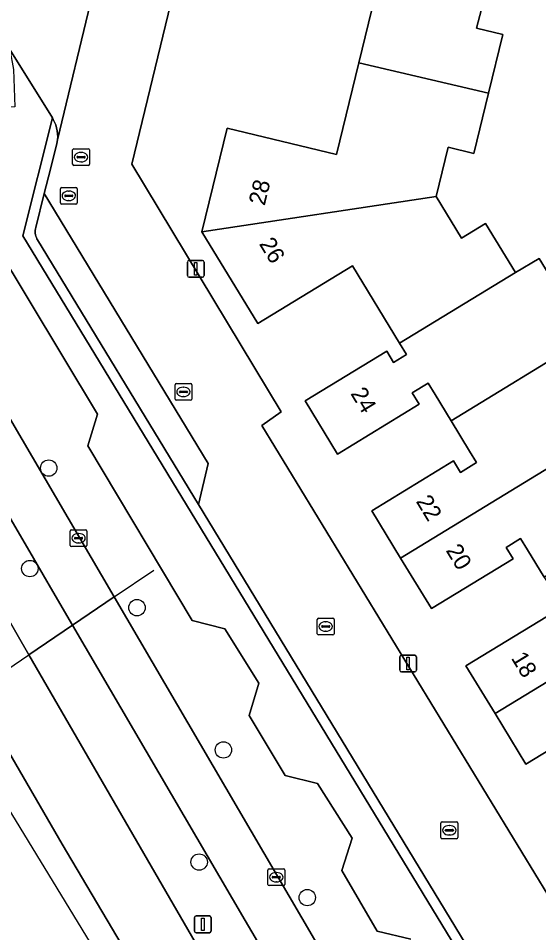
# Model space of a CAD drawing. Extents: x 157767 to 159172, y 387839 to 389425.
# Drawn here: x 158129.2 to 158160.3, y 388348.6 to 388403.1 of the extents above; entities that cross this region are included whole.
import ezdxf

# ---------------------------------------------------------------- set-up
doc = ezdxf.new("R2010")
doc.units = 0
for name, color, linetype in [('IMGEO_Berm_groen', 7, 'Continuous'), ('IMGEO_Boom', 7, 'Continuous'), ('IMGEO_Duiker', 7, 'Continuous'), ('IMGEO_Erf', 7, 'Continuous'), ('IMGEO_Fietspad_gesloten', 7, 'Continuous'), ('IMGEO_Fietspad_open', 7, 'Continuous'), ('IMGEO_Groenvoorziening', 7, 'Continuous'), ('IMGEO_Kolk', 7, 'Continuous'), ('IMGEO_Lichtmast', 7, 'Continuous'), ('IMGEO_Muur', 7, 'Continuous'), ('IMGEO_Pand', 7, 'Continuous'), ('IMGEO_Pand_nummerreeks', 7, 'Continuous'), ('IMGEO_Parkeervlak_open', 7, 'Continuous'), ('IMGEO_Rijbaan_lokaal_open', 7, 'Continuous'), ('IMGEO_Rijbaan_regionaal_gesloten', 7, 'Continuous'), ('IMGEO_Rioolput', 7, 'Continuous'), ('IMGEO_Voetpad_open', 7, 'Continuous')]:
    doc.layers.add(name, color=color, linetype=linetype)

msp = doc.modelspace()

# ---------------------------------------------------------------- linework, layer by layer
at = {"layer": 'IMGEO_Berm_groen'}
for points in [[(158093.596, 388437.697), (158077.696, 388467.86), (158066.3, 388489.348), (158060.675, 388500), (158059.824, 388501.559), (158060.092, 388498.304), (158060.284, 388498.409), (158061.294, 388496.567), (158060.28, 388496.011), (158060.757, 388490.208), (158067.746, 388475.595), (158073.282, 388464.018), (158077.309, 388457.044), (158080.74, 388450.845), (158117.028, 388387.52), (158126.188, 388371.462), (158129.845, 388365.121), (158132.45, 388366.885), (158131.292, 388368.887), (158130.136, 388370.89), (158116.54, 388394.144), (158109.829, 388406.303), (158099.787, 388425.751)], [(158153.286, 388331.356), (158142.759, 388349.282), (158132.45, 388366.885), (158129.845, 388365.121), (158139.769, 388348), (158157.789, 388317.741), (158173.795, 388291.448), (158178.959, 388283.153), (158180.756, 388284.205), (158178.868, 388289.086), (158165.181, 388311.658)]]:
    msp.add_lwpolyline(points, close=True, dxfattribs=at)
at = {"layer": 'IMGEO_Boom'}
for centre in [(158131.037, 388376.248), (158129.913, 388370.263), (158136.3, 388367.931), (158141.455, 388359.45), (158140.006, 388352.769), (158146.455, 388350.649)]:
    msp.add_circle(centre, 0.489, dxfattribs=at)
at = {"layer": 'IMGEO_Duiker'}
msp.add_lwpolyline([(158125.103, 388361.908), (158125.146, 388361.937), (158126.715, 388363), (158129.845, 388365.121), (158132.45, 388366.885), (158134.936, 388368.569), (158137.301, 388370.172)], dxfattribs=at)
at = {"layer": 'IMGEO_Erf'}
for points in [[(158141.098, 388415.471), (158135.994, 388394.364), (158144.897, 388379.594), (158143.742, 388378.793), (158169.317, 388336.817)], [(158160.58, 388369.753), (158159.594, 388371.37), (158159.177, 388372.054), (158158.306, 388371.523), (158158.722, 388370.839), (158153.854, 388367.872), (158152.017, 388370.886), (158150.297, 388373.709), (158155.165, 388376.676), (158155.582, 388375.993), (158156.545, 388376.58), (158156.129, 388377.263), (158155.027, 388379.072), (158154.073, 388380.638), (158153.657, 388381.322), (158152.702, 388380.74), (158153.118, 388380.056), (158148.25, 388377.09), (158146.319, 388380.259), (158151.188, 388383.226), (158151.604, 388382.543), (158152.376, 388383.014), (158151.961, 388383.695), (158149.147, 388388.314), (158143.498, 388384.871), (158140.169, 388390.335), (158141.671, 388396.521), (158148.204, 388394.933), (158149.535, 388400.41), (158150.867, 388405.887)], [(158157.317, 388405.425), (158156.544, 388402.467), (158158.109, 388402.086), (158157.261, 388398.598), (158156.388, 388395.006), (158154.849, 388395.38), (158154.131, 388392.43), (158155.645, 388389.947), (158157.089, 388390.827), (158158.87, 388387.903), (158160.28, 388388.751), (158163.159, 388384.027), (158165.981, 388379.396), (158168.803, 388374.765), (158171.625, 388370.134), (158174.978, 388372.178), (158177.801, 388367.546), (158174.448, 388365.502), (158177.27, 388360.871), (158180.092, 388356.24), (158182.914, 388351.609), (158185.8, 388346.873)], [(158164.35, 388361.572), (158159.482, 388358.605), (158157.648, 388361.615), (158155.916, 388364.457), (158160.784, 388367.424)]]:
    msp.add_lwpolyline(points, dxfattribs=at)
at = {"layer": 'IMGEO_Fietspad_gesloten'}
msp.add_lwpolyline([(158077.696, 388467.86), (158093.596, 388437.697), (158099.787, 388425.751), (158109.829, 388406.303), (158116.54, 388394.144), (158130.136, 388370.89), (158131.292, 388368.887), (158132.45, 388366.885), (158134.936, 388368.569), (158119.086, 388395.663), (158117.484, 388398.656), (158113.772, 388405.372), (158099.445, 388433.055), (158096.584, 388438.321), (158064.182, 388500)], dxfattribs=at)
msp.add_lwpolyline([(158175.742, 388299.912), (158162.359, 388321.986), (158152.031, 388339.346), (158134.936, 388368.569), (158132.45, 388366.885), (158142.759, 388349.282), (158153.286, 388331.356), (158165.181, 388311.658), (158178.868, 388289.086), (158188.453, 388273.59), (158199.34, 388257.164), (158201.801, 388253.451), (158204.172, 388250), (158207.773, 388244.758), (158210.203, 388246.361), (158201.818, 388258.573), (158195.13, 388268.765), (158188.418, 388279.263)], close=True, dxfattribs=at)
at = {"layer": 'IMGEO_Fietspad_open'}
msp.add_lwpolyline([(158109.579, 388433.031), (158117.583, 388419.75), (158128.726, 388401.202), (158131.254, 388397.124), (158131.309, 388397.033), (158131.391, 388396.872), (158131.459, 388396.705), (158131.511, 388396.533), (158131.548, 388396.356), (158131.569, 388396.177), (158131.573, 388395.997), (158131.562, 388395.817), (158133.657, 388404.502)], dxfattribs=at)
at = {"layer": 'IMGEO_Groenvoorziening'}
for points in [[(158108.113, 388434.305), (158101.745, 388435.024), (158101.62, 388435.033), (158101.495, 388435.03), (158101.37, 388435.016), (158101.248, 388434.991), (158101.127, 388434.956), (158101.011, 388434.909), (158100.899, 388434.853), (158100.793, 388434.787), (158100.693, 388434.711), (158100.6, 388434.627), (158100.515, 388434.535), (158100.449, 388434.45), (158099.445, 388433.055), (158113.772, 388405.372), (158117.484, 388398.656), (158119.086, 388395.663), (158134.936, 388368.569), (158152.031, 388339.346)], [(158175.446, 388314.592), (158129.494, 388390.09), (158131.254, 388397.124), (158128.726, 388401.202), (158128.931, 388400.006), (158129.021, 388397.788), (158127.944, 388397.706), (158126.885, 388397.853), (158125.71, 388393.121), (158133.951, 388379.467), (158133.376, 388377.573), (158139.588, 388367.158), (158141.543, 388366.666), (158143.57, 388363.424), (158142.99, 388361.495), (158145.126, 388357.922), (158147.067, 388357.45), (158149.128, 388354.196), (158148.513, 388352.268), (158150.628, 388348.658), (158152.625, 388348.163)], [(158152.625, 388348.163), (158150.628, 388348.658), (158148.513, 388352.268), (158149.128, 388354.196), (158147.067, 388357.45), (158145.126, 388357.922), (158142.99, 388361.495), (158143.57, 388363.424), (158141.543, 388366.666), (158139.588, 388367.158), (158133.376, 388377.573), (158133.951, 388379.467), (158125.71, 388393.121), (158126.885, 388397.853)]]:
    msp.add_lwpolyline(points, dxfattribs=at)
at = {"layer": 'IMGEO_Kolk'}
for p, q in [((158132.539, 388395.285), (158133.391, 388395.285)), ((158132.464, 388394.359), (158132.464, 388395.211)), ((158132.723, 388394.779), (158132.723, 388394.791)), ((158133.161, 388394.742), (158132.763, 388394.742)), ((158132.766, 388394.828), (158133.164, 388394.828)), ((158132.952, 388395.065), (158132.977, 388395.065)), ((158133.207, 388394.791), (158133.207, 388394.779)), ((158133.465, 388395.211), (158133.465, 388394.359)), ((158133.391, 388394.285), (158132.539, 388394.285)), ((158132.975, 388394.505), (158132.95, 388394.505)), ((158138.567, 388380.365), (158138.567, 388381.217)), ((158138.642, 388381.291), (158139.494, 388381.291)), ((158139.568, 388381.217), (158139.568, 388380.365)), ((158138.826, 388380.785), (158138.826, 388380.797)), ((158139.264, 388380.748), (158138.866, 388380.748)), ((158138.869, 388380.834), (158139.267, 388380.834)), ((158139.055, 388381.071), (158139.08, 388381.071)), ((158139.31, 388380.797), (158139.31, 388380.785)), ((158139.494, 388380.291), (158138.642, 388380.291)), ((158139.078, 388380.511), (158139.053, 388380.511)), ((158132.318, 388371.645), (158132.318, 388372.497)), ((158132.393, 388372.571), (158133.245, 388372.571)), ((158133.319, 388372.497), (158133.319, 388371.645)), ((158132.577, 388372.065), (158132.577, 388372.077)), ((158133.015, 388372.028), (158132.617, 388372.028)), ((158132.62, 388372.114), (158133.018, 388372.114)), ((158132.806, 388372.351), (158132.831, 388372.351)), ((158133.061, 388372.077), (158133.061, 388372.065)), ((158133.245, 388371.571), (158132.393, 388371.571)), ((158132.829, 388371.791), (158132.804, 388371.791)), ((158147.053, 388366.381), (158147.053, 388367.233)), ((158147.128, 388367.307), (158147.98, 388367.307)), ((158147.541, 388367.087), (158147.566, 388367.087)), ((158148.054, 388367.233), (158148.054, 388366.381)), ((158147.312, 388366.801), (158147.312, 388366.813)), ((158147.75, 388366.764), (158147.352, 388366.764)), ((158147.355, 388366.85), (158147.753, 388366.85)), ((158147.564, 388366.527), (158147.539, 388366.527)), ((158147.796, 388366.813), (158147.796, 388366.801)), ((158147.98, 388366.307), (158147.128, 388366.307)), ((158154.423, 388354.235), (158154.423, 388355.087)), ((158154.498, 388355.161), (158155.35, 388355.161)), ((158154.911, 388354.941), (158154.936, 388354.941)), ((158155.424, 388355.087), (158155.424, 388354.235)), ((158154.682, 388354.655), (158154.682, 388354.667)), ((158155.12, 388354.618), (158154.722, 388354.618)), ((158154.725, 388354.704), (158155.123, 388354.704)), ((158154.934, 388354.381), (158154.909, 388354.381)), ((158155.166, 388354.667), (158155.166, 388354.655)), ((158155.35, 388354.161), (158154.498, 388354.161)), ((158144.108, 388351.439), (158144.108, 388352.291)), ((158144.183, 388352.365), (158145.035, 388352.365)), ((158145.109, 388352.291), (158145.109, 388351.439)), ((158144.367, 388351.859), (158144.367, 388351.871)), ((158144.805, 388351.822), (158144.407, 388351.822)), ((158144.41, 388351.908), (158144.808, 388351.908)), ((158144.596, 388352.145), (158144.621, 388352.145)), ((158144.851, 388351.871), (158144.851, 388351.859)), ((158145.035, 388351.365), (158144.183, 388351.365)), ((158144.619, 388351.585), (158144.594, 388351.585))]:
    msp.add_line(p, q, dxfattribs=at)
for points in [[(158132.539, 388395.285), (158133.391, 388395.285)], [(158132.464, 388394.359), (158132.464, 388395.211)], [(158133.465, 388395.211), (158133.465, 388394.359)], [(158133.391, 388394.285), (158132.539, 388394.285)], [(158138.567, 388380.365), (158138.567, 388381.217)], [(158138.642, 388381.291), (158139.494, 388381.291)], [(158139.568, 388381.217), (158139.568, 388380.365)], [(158139.494, 388380.291), (158138.642, 388380.291)], [(158132.318, 388371.645), (158132.318, 388372.497)], [(158132.393, 388372.571), (158133.245, 388372.571)], [(158133.319, 388372.497), (158133.319, 388371.645)], [(158133.245, 388371.571), (158132.393, 388371.571)], [(158147.053, 388366.381), (158147.053, 388367.233)], [(158147.128, 388367.307), (158147.98, 388367.307)], [(158148.054, 388367.233), (158148.054, 388366.381)], [(158147.98, 388366.307), (158147.128, 388366.307)], [(158154.423, 388354.235), (158154.423, 388355.087)], [(158154.498, 388355.161), (158155.35, 388355.161)], [(158155.424, 388355.087), (158155.424, 388354.235)], [(158155.35, 388354.161), (158154.498, 388354.161)], [(158144.108, 388351.439), (158144.108, 388352.291)], [(158144.183, 388352.365), (158145.035, 388352.365)], [(158145.109, 388352.291), (158145.109, 388351.439)], [(158145.035, 388351.365), (158144.183, 388351.365)]]:
    msp.add_lwpolyline(points, dxfattribs=at)
for centre, radius, start, end in [((158132.541, 388395.209), 0.0765, 91.552, 178.448), ((158132.541, 388395.209), 0.0765, 91.552, 178.448), ((158133.389, 388395.209), 0.0765, 1.552, 88.448), ((158133.389, 388395.209), 0.0765, 1.552, 88.448), ((158132.763, 388394.788), 0.0403, 85.8775, 175.7526), ((158132.76, 388394.778), 0.0366, 178.938, 274.7102), ((158133.164, 388394.785), 0.043, 264.8664, 352.4533), ((158133.168, 388394.79), 0.0386, 1.7309, 96.639), ((158132.541, 388394.361), 0.0765, 181.552, 268.448), ((158132.541, 388394.361), 0.0765, 181.552, 268.448), ((158133.389, 388394.361), 0.0765, 271.552, 358.448), ((158133.389, 388394.361), 0.0765, 271.552, 358.448), ((158138.644, 388381.215), 0.0765, 91.552, 178.448), ((158138.644, 388381.215), 0.0765, 91.552, 178.448), ((158139.492, 388381.215), 0.0765, 1.552, 88.448), ((158139.492, 388381.215), 0.0765, 1.552, 88.448), ((158138.866, 388380.794), 0.0403, 85.8775, 175.7526), ((158138.863, 388380.784), 0.0366, 178.938, 274.7102), ((158139.267, 388380.791), 0.043, 264.8664, 352.4533), ((158139.271, 388380.796), 0.0386, 1.7309, 96.639), ((158138.644, 388380.367), 0.0765, 181.552, 268.448), ((158138.644, 388380.367), 0.0765, 181.552, 268.448), ((158139.492, 388380.367), 0.0765, 271.552, 358.448), ((158139.492, 388380.367), 0.0765, 271.552, 358.448), ((158132.395, 388372.495), 0.0765, 91.552, 178.448), ((158132.395, 388372.495), 0.0765, 91.552, 178.448), ((158133.243, 388372.495), 0.0765, 1.552, 88.448), ((158133.243, 388372.495), 0.0765, 1.552, 88.448), ((158132.617, 388372.074), 0.0403, 85.8775, 175.7526), ((158132.614, 388372.064), 0.0366, 178.938, 274.7102), ((158133.018, 388372.071), 0.043, 264.8664, 352.4533), ((158133.022, 388372.076), 0.0386, 1.7309, 96.639), ((158132.395, 388371.647), 0.0765, 181.552, 268.448), ((158132.395, 388371.647), 0.0765, 181.552, 268.448), ((158133.243, 388371.647), 0.0765, 271.552, 358.448), ((158133.243, 388371.647), 0.0765, 271.552, 358.448), ((158147.13, 388367.231), 0.0765, 91.552, 178.448), ((158147.13, 388367.231), 0.0765, 91.552, 178.448), ((158147.978, 388367.231), 0.0765, 1.552, 88.448), ((158147.978, 388367.231), 0.0765, 1.552, 88.448), ((158147.13, 388366.383), 0.0765, 181.552, 268.448), ((158147.13, 388366.383), 0.0765, 181.552, 268.448), ((158147.352, 388366.81), 0.0403, 85.8775, 175.7526), ((158147.349, 388366.8), 0.0366, 178.938, 274.7102), ((158147.753, 388366.807), 0.043, 264.8664, 352.4533), ((158147.757, 388366.812), 0.0386, 1.7309, 96.639), ((158147.978, 388366.383), 0.0765, 271.552, 358.448), ((158147.978, 388366.383), 0.0765, 271.552, 358.448), ((158154.5, 388355.085), 0.0765, 91.552, 178.448), ((158154.5, 388355.085), 0.0765, 91.552, 178.448), ((158155.348, 388355.085), 0.0765, 1.552, 88.448), ((158155.348, 388355.085), 0.0765, 1.552, 88.448), ((158154.722, 388354.664), 0.0403, 85.8775, 175.7526), ((158154.719, 388354.654), 0.0366, 178.938, 274.7102), ((158155.123, 388354.661), 0.043, 264.8664, 352.4533), ((158155.127, 388354.666), 0.0386, 1.7309, 96.639), ((158154.5, 388354.237), 0.0765, 181.552, 268.448), ((158154.5, 388354.237), 0.0765, 181.552, 268.448), ((158155.348, 388354.237), 0.0765, 271.552, 358.448), ((158155.348, 388354.237), 0.0765, 271.552, 358.448), ((158144.185, 388352.289), 0.0765, 91.552, 178.448), ((158144.185, 388352.289), 0.0765, 91.552, 178.448), ((158145.033, 388352.289), 0.0765, 1.552, 88.448), ((158145.033, 388352.289), 0.0765, 1.552, 88.448), ((158144.407, 388351.868), 0.0403, 85.8775, 175.7526), ((158144.404, 388351.858), 0.0366, 178.938, 274.7102), ((158144.808, 388351.865), 0.043, 264.8664, 352.4533), ((158144.812, 388351.87), 0.0386, 1.7309, 96.639), ((158144.185, 388351.441), 0.0765, 181.552, 268.448), ((158144.185, 388351.441), 0.0765, 181.552, 268.448), ((158145.033, 388351.441), 0.0765, 271.552, 358.448), ((158145.033, 388351.441), 0.0765, 271.552, 358.448)]:
    msp.add_arc(centre, radius, start, end, dxfattribs=at)
for centre, major_axis, ratio, start_param, end_param in [((158132.951, 388394.785), (-0.387, 0.002), 0.722429, 4.712389, 7.853982), ((158132.976, 388394.785), (-0.39, 0.002), 0.717154, 1.570796, 4.712389), ((158139.054, 388380.791), (-0.387, 0.002), 0.722429, 4.712389, 7.853982), ((158139.079, 388380.791), (-0.39, 0.002), 0.717154, 1.570796, 4.712389), ((158132.805, 388372.071), (-0.387, 0.002), 0.722429, 4.712389, 7.853982), ((158132.83, 388372.071), (-0.39, 0.002), 0.717154, 1.570796, 4.712389), ((158147.54, 388366.807), (-0.387, 0.002), 0.722429, 4.712389, 7.853982), ((158147.565, 388366.807), (-0.39, 0.002), 0.717154, 1.570796, 4.712389), ((158154.91, 388354.661), (-0.387, 0.002), 0.722429, 4.712389, 7.853982), ((158154.935, 388354.661), (-0.39, 0.002), 0.717154, 1.570796, 4.712389), ((158144.595, 388351.865), (-0.387, 0.002), 0.722429, 4.712389, 7.853982), ((158144.62, 388351.865), (-0.39, 0.002), 0.717154, 1.570796, 4.712389)]:
    msp.add_ellipse(centre, major_axis=major_axis, ratio=ratio, start_param=start_param, end_param=end_param, dxfattribs=at)
at = {"layer": 'IMGEO_Lichtmast'}
for p, q in [((158139.308, 388387.73), (158139.308, 388388.53)), ((158139.308, 388388.53), (158139.308, 388387.73)), ((158139.408, 388388.63), (158140.198, 388388.63)), ((158140.198, 388388.63), (158139.408, 388388.63)), ((158140.298, 388388.53), (158140.298, 388387.73)), ((158140.298, 388387.73), (158140.298, 388388.53)), ((158140.198, 388387.63), (158139.408, 388387.63)), ((158139.408, 388387.63), (158140.198, 388387.63)), ((158151.968, 388364.199), (158151.968, 388364.999)), ((158151.968, 388364.999), (158151.968, 388364.199)), ((158152.068, 388365.099), (158152.858, 388365.099)), ((158152.858, 388365.099), (158152.068, 388365.099)), ((158152.958, 388364.999), (158152.958, 388364.199)), ((158152.958, 388364.199), (158152.958, 388364.999)), ((158152.858, 388364.099), (158152.068, 388364.099)), ((158152.068, 388364.099), (158152.858, 388364.099)), ((158139.828, 388349.556), (158140.618, 388349.556)), ((158140.618, 388349.556), (158139.828, 388349.556)), ((158139.728, 388348.656), (158139.728, 388349.456)), ((158139.728, 388349.456), (158139.728, 388348.656)), ((158140.718, 388349.456), (158140.718, 388348.656)), ((158140.718, 388348.656), (158140.718, 388349.456)), ((158140.618, 388348.556), (158139.828, 388348.556)), ((158139.828, 388348.556), (158140.618, 388348.556))]:
    msp.add_line(p, q, dxfattribs=at)
for points in [[(158139.728, 388388.505), (158139.878, 388388.505), (158139.878, 388387.755), (158139.728, 388387.755), (158139.728, 388388.505)], [(158152.388, 388364.974), (158152.538, 388364.974), (158152.538, 388364.224), (158152.388, 388364.224), (158152.388, 388364.974)], [(158140.148, 388349.431), (158140.298, 388349.431), (158140.298, 388348.681), (158140.148, 388348.681), (158140.148, 388349.431)]]:
    msp.add_lwpolyline(points, dxfattribs=at)
for centre, start, end in [((158139.408, 388388.53), 90, 180), ((158139.408, 388388.53), 90, 180), ((158140.198, 388388.53), 0, 90), ((158140.198, 388388.53), 360, 90), ((158139.408, 388387.73), 180, 270), ((158139.408, 388387.73), 180, 270), ((158140.198, 388387.73), 270, 0), ((158140.198, 388387.73), 270, 0), ((158152.068, 388364.999), 90, 180), ((158152.068, 388364.999), 90, 180), ((158152.858, 388364.999), 0, 90), ((158152.858, 388364.999), 360, 90), ((158152.068, 388364.199), 180, 270), ((158152.068, 388364.199), 180, 270), ((158152.858, 388364.199), 270, 0), ((158152.858, 388364.199), 270, 0), ((158139.828, 388349.456), 90, 180), ((158139.828, 388349.456), 90, 180), ((158140.618, 388349.456), 0, 90), ((158140.618, 388349.456), 360, 90), ((158139.828, 388348.656), 180, 270), ((158139.828, 388348.656), 180, 270), ((158140.618, 388348.656), 270, 0), ((158140.618, 388348.656), 270, 0)]:
    msp.add_arc(centre, 0.1, start, end, dxfattribs=at)
at = {"layer": 'IMGEO_Muur'}
msp.add_lwpolyline([(158126.885, 388397.853), (158125.71, 388393.121), (158133.951, 388379.467), (158133.376, 388377.573), (158139.588, 388367.158), (158141.543, 388366.666), (158143.57, 388363.424), (158142.99, 388361.495), (158145.126, 388357.922), (158147.067, 388357.45), (158149.128, 388354.196), (158148.513, 388352.268), (158150.628, 388348.658), (158152.625, 388348.163)], dxfattribs=at)
at = {"layer": 'IMGEO_Pand'}
for points in [[(158149.535, 388400.41), (158157.261, 388398.598), (158158.109, 388402.086), (158156.544, 388402.467), (158157.317, 388405.425), (158145.839, 388413.615), (158144.346, 388407.472), (158150.867, 388405.887)], [(158140.169, 388390.335), (158154.131, 388392.43), (158154.849, 388395.38), (158156.388, 388395.006), (158157.261, 388398.598), (158149.535, 388400.41), (158148.204, 388394.933), (158141.671, 388396.521)], [(158140.169, 388390.335), (158143.498, 388384.871), (158149.147, 388388.314), (158151.961, 388383.695), (158158.87, 388387.903), (158157.089, 388390.827), (158155.645, 388389.947), (158154.131, 388392.43)], [(158163.159, 388384.027), (158160.28, 388388.751), (158158.87, 388387.903), (158151.961, 388383.695), (158152.376, 388383.014), (158151.604, 388382.543), (158151.188, 388383.226), (158146.319, 388380.259), (158148.25, 388377.09), (158153.118, 388380.056), (158152.702, 388380.74), (158153.657, 388381.322), (158154.073, 388380.638), (158155.027, 388379.072)], [(158163.159, 388384.027), (158155.027, 388379.072), (158156.129, 388377.263), (158156.545, 388376.58), (158155.582, 388375.993), (158155.165, 388376.676), (158150.297, 388373.709), (158152.017, 388370.886), (158165.981, 388379.396)], [(158152.017, 388370.886), (158153.854, 388367.872), (158158.722, 388370.839), (158158.306, 388371.523), (158159.177, 388372.054), (158159.594, 388371.37), (158160.58, 388369.753), (158168.803, 388374.765), (158165.981, 388379.396)], [(158171.625, 388370.134), (158168.803, 388374.765), (158160.58, 388369.753), (158161.67, 388367.964), (158162.086, 388367.281), (158161.201, 388366.741), (158160.784, 388367.424), (158155.916, 388364.457), (158157.648, 388361.615)], [(158174.448, 388365.502), (158177.801, 388367.546), (158174.978, 388372.178), (158171.625, 388370.134), (158157.648, 388361.615), (158159.482, 388358.605), (158164.35, 388361.572), (158163.934, 388362.256), (158164.778, 388362.771), (158165.195, 388362.087), (158166.183, 388360.465)]]:
    msp.add_lwpolyline(points, close=True, dxfattribs=at)
at = {"layer": 'IMGEO_Parkeervlak_open'}
msp.add_lwpolyline([(158130.772, 388392.615), (158130.262, 388390.593), (158130.244, 388390.508), (158130.234, 388390.421), (158130.232, 388390.335), (158130.238, 388390.248), (158130.251, 388390.162), (158130.272, 388390.077), (158130.3, 388389.995), (158130.336, 388389.916), (158130.375, 388389.846), (158139.968, 388374.072), (158140.538, 388376.528)], close=True, dxfattribs=at)
at = {"layer": 'IMGEO_Rijbaan_lokaal_open'}
for points in [[(158170.612, 388337.516), (158169.317, 388336.817), (158143.742, 388378.793), (158144.897, 388379.594), (158135.994, 388394.364), (158141.098, 388415.471), (158153.984, 388423.292), (158153.056, 388425.158), (158180.797, 388442.173), (158182.041, 388442.936), (158183.168, 388447.406), (158193.554, 388453.846), (158206.398, 388461.811), (158203.803, 388466.059), (158203.622, 388465.947), (158177.876, 388450.031)], [(158136.945, 388418.095), (158133.657, 388404.502), (158131.562, 388395.817), (158131.526, 388395.604), (158131.141, 388394.073), (158130.772, 388392.615), (158140.538, 388376.528), (158139.968, 388374.072), (158163.532, 388335.322), (158165.985, 388334.699), (158178.511, 388314.19), (158180.125, 388313.63), (158186.808, 388311.343), (158191.591, 388309.706)]]:
    msp.add_lwpolyline(points, dxfattribs=at)
at = {"layer": 'IMGEO_Rijbaan_regionaal_gesloten'}
msp.add_lwpolyline([(158127.081, 388358.439), (158199.528, 388239.724), (158200.59, 388240.362), (158192.107, 388254.146), (158166.877, 388295.262), (158150.236, 388322.758), (158131.842, 388353.83), (158117.262, 388378.952), (158097.857, 388412.932), (158070.009, 388461.63), (158044.126, 388506.669), (158040.061, 388513.776), (158019.492, 388549.641), (158005.756, 388573.613), (158005.68, 388573.566), (158005.013, 388573.158), (158051.596, 388490.837), (158089.79, 388423.845), (158099.803, 388406.283)], close=True, dxfattribs=at)
for points in [[(158070.009, 388461.63), (158097.857, 388412.932), (158117.262, 388378.952), (158131.842, 388353.83), (158150.236, 388322.758)], [(158139.769, 388348), (158129.845, 388365.121), (158126.188, 388371.462), (158117.028, 388387.52), (158080.74, 388450.845), (158077.309, 388457.044)]]:
    msp.add_lwpolyline(points, dxfattribs=at)
at = {"layer": 'IMGEO_Rioolput'}
for p, q in [((158131.735, 388392.053), (158131.735, 388392.905)), ((158131.81, 388392.979), (158132.662, 388392.979)), ((158132.223, 388392.759), (158132.248, 388392.759)), ((158132.736, 388392.905), (158132.736, 388392.053)), ((158131.994, 388392.473), (158131.994, 388392.485)), ((158132.432, 388392.436), (158132.034, 388392.436)), ((158132.037, 388392.522), (158132.435, 388392.522)), ((158132.246, 388392.199), (158132.221, 388392.199)), ((158132.478, 388392.485), (158132.478, 388392.473)), ((158132.662, 388391.979), (158131.81, 388391.979))]:
    msp.add_line(p, q, dxfattribs=at)
for points in [[(158131.735, 388392.053), (158131.735, 388392.905)], [(158131.81, 388392.979), (158132.662, 388392.979)], [(158132.736, 388392.905), (158132.736, 388392.053)], [(158132.662, 388391.979), (158131.81, 388391.979)]]:
    msp.add_lwpolyline(points, dxfattribs=at)
for centre, radius, start, end in [((158131.812, 388392.903), 0.0765, 91.552, 178.448), ((158131.812, 388392.903), 0.0765, 91.552, 178.448), ((158132.66, 388392.903), 0.0765, 1.552, 88.448), ((158132.66, 388392.903), 0.0765, 1.552, 88.448), ((158131.812, 388392.055), 0.0765, 181.552, 268.448), ((158131.812, 388392.055), 0.0765, 181.552, 268.448), ((158132.034, 388392.482), 0.0403, 85.8775, 175.7526), ((158132.031, 388392.472), 0.0366, 178.938, 274.7102), ((158132.435, 388392.479), 0.043, 264.8664, 352.4533), ((158132.439, 388392.484), 0.0386, 1.7309, 96.639), ((158132.66, 388392.055), 0.0765, 271.552, 358.448), ((158132.66, 388392.055), 0.0765, 271.552, 358.448)]:
    msp.add_arc(centre, radius, start, end, dxfattribs=at)
for centre, major_axis, ratio, start_param, end_param in [((158132.222, 388392.479), (-0.387, 0.002), 0.722429, 4.712389, 7.853982), ((158132.247, 388392.479), (-0.39, 0.002), 0.717154, 1.570796, 4.712389)]:
    msp.add_ellipse(centre, major_axis=major_axis, ratio=ratio, start_param=start_param, end_param=end_param, dxfattribs=at)
at = {"layer": 'IMGEO_Voetpad_open'}
msp.add_lwpolyline([(158163.532, 388335.322), (158139.968, 388374.072), (158130.375, 388389.846), (158130.336, 388389.916), (158130.3, 388389.995), (158130.272, 388390.077), (158130.251, 388390.162), (158130.238, 388390.248), (158130.232, 388390.335), (158130.234, 388390.421), (158130.244, 388390.508), (158130.262, 388390.593), (158130.772, 388392.615), (158131.141, 388394.073), (158131.526, 388395.604), (158131.562, 388395.817), (158131.573, 388395.997), (158131.569, 388396.177), (158131.548, 388396.356), (158131.511, 388396.533), (158131.459, 388396.705), (158131.391, 388396.872), (158131.309, 388397.033), (158131.254, 388397.124), (158129.494, 388390.09), (158175.446, 388314.592)], dxfattribs=at)

# ---------------------------------------------------------------- texts
at = {"layer": 'IMGEO_Pand_nummerreeks'}
for s, rotation, p in [('28', 76.3436, (158143.913, 388391.853)), ('26', 301.36, (158143.554, 388389.62)), ('24', 301.3556, (158149.006, 388380.692)), ('22', 301.3576, (158152.907, 388374.269)), ('20', 301.3576, (158154.688, 388371.345)), ('18', 301.3566, (158158.578, 388364.931))]:
    msp.add_text(s, height=1, rotation=rotation, dxfattribs=at).set_placement(p)

doc.saveas('drawing.dxf')
